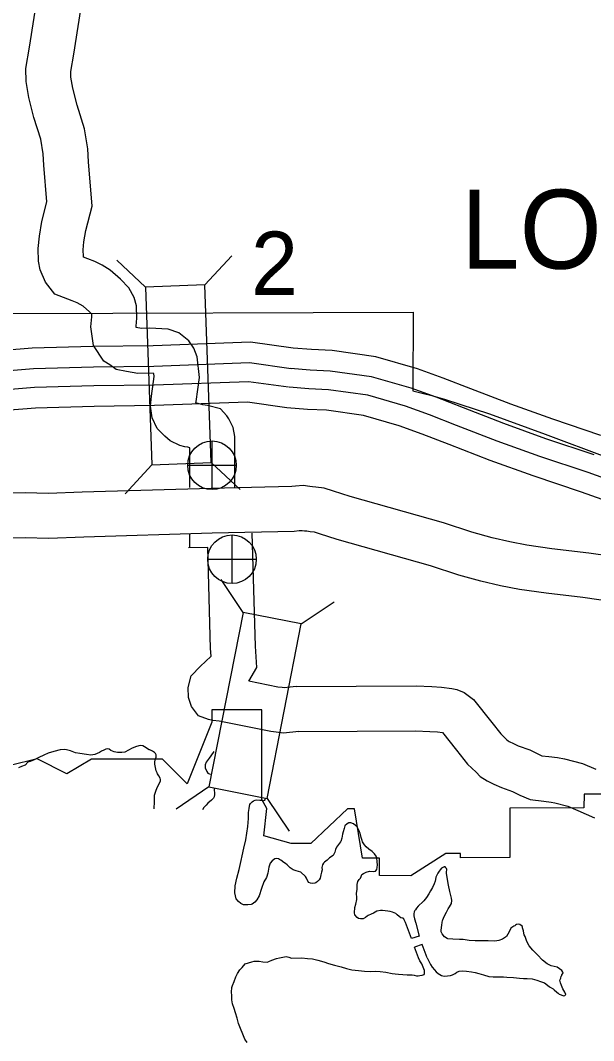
# Model space of a CAD drawing. Extents: x 1374139 to 1377472, y 1168351 to 1170484.
# Drawn here: x 1374342.2 to 1374380.5, y 1170108.2 to 1170176.4 of the extents above; entities that cross this region are included whole.
import ezdxf

# ---------------------------------------------------------------- set-up
doc = ezdxf.new("R2010")
doc.units = 0
doc.layers.add('Default', color=7, linetype='Continuous')

msp = doc.modelspace()

# ---------------------------------------------------------------- linework, layer by layer
at = {"layer": 'Default'}
for p, q in [((1374354.51, 1170158.728), (1374356.309, 1170160.66)), ((1374350.552, 1170158.587), (1374348.62, 1170160.387)), ((1374354.991, 1170145.055), (1374354.991, 1170148.305)), ((1374350.974, 1170146.715), (1374349.175, 1170144.783)), ((1374353.366, 1170146.68), (1374356.616, 1170146.68)), ((1374354.932, 1170146.855), (1374356.864, 1170145.056)), ((1374356.328, 1170138.779), (1374356.328, 1170142.029)), ((1374354.703, 1170140.404), (1374357.953, 1170140.404)), ((1374357.074, 1170136.849), (1374355.601, 1170139.04)), ((1374360.96, 1170136.087), (1374363.151, 1170137.559)), ((1374354.787, 1170125.191), (1374352.596, 1170123.718)), ((1374358.673, 1170124.429), (1374360.146, 1170122.238))]:
    msp.add_line(p, q, dxfattribs=at)
for points in [[(1374353.509, 1170145.193), (1374353.51, 1170147.852), (1374353.381, 1170147.888), (1374353.185, 1170147.904), (1374352.831, 1170148.01), (1374352.203, 1170148.31), (1374351.827, 1170148.623), (1374351.318, 1170149.141), (1374350.997, 1170149.855), (1374350.873, 1170150.636), (1374350.943, 1170151.302), (1374351.126, 1170152.608), (1374351.105, 1170152.815), (1374350.797, 1170152.828), (1374350.026, 1170152.804), (1374349.281, 1170152.948), (1374348.578, 1170153.082), (1374348.17, 1170153.389), (1374347.762, 1170153.623), (1374347.057, 1170154.682), (1374346.899, 1170155.919), (1374346.967, 1170156.605), (1374346.962, 1170156.771), (1374346.806, 1170156.926), (1374346.377, 1170157.308), (1374346.182, 1170157.43), (1374345.978, 1170157.531), (1374345.637, 1170157.656), (1374344.475, 1170158.103), (1374343.869, 1170158.911), (1374343.495, 1170159.733), (1374343.397, 1170160.316), (1374343.371, 1170161.17), (1374343.454, 1170161.979), (1374343.604, 1170162.97), (1374343.944, 1170164.268), (1374343.75, 1170166.735), (1374343.7, 1170167.484), (1374343.543, 1170168.457), (1374343.087, 1170169.912), (1374342.743, 1170171.257), (1374342.569, 1170172.308), (1374342.542, 1170173.189), (1374342.785, 1170174.617), (1374343.826, 1170181.294)], [(1374356.509, 1170145.213), (1374356.51, 1170148.608), (1374356.401, 1170149.203), (1374356.117, 1170149.786), (1374355.974, 1170149.988), (1374355.548, 1170150.457), (1374354.69, 1170150.675), (1374354.385, 1170150.723), (1374353.912, 1170150.854), (1374353.921, 1170150.937), (1374354.147, 1170152.552), (1374354.007, 1170153.918), (1374353.77, 1170154.497), (1374353.431, 1170155.001), (1374352.777, 1170155.526), (1374352.061, 1170155.778), (1374350.813, 1170155.83), (1374350.267, 1170155.813), (1374349.928, 1170155.878), (1374349.918, 1170155.961), (1374349.971, 1170156.502), (1374349.946, 1170157.322), (1374349.784, 1170157.876), (1374349.439, 1170158.538), (1374348.864, 1170159.11), (1374348.184, 1170159.717), (1374347.645, 1170160.054), (1374347.16, 1170160.293), (1374346.692, 1170160.464), (1374346.409, 1170160.573), (1374346.389, 1170160.617), (1374346.375, 1170161.062), (1374346.431, 1170161.601), (1374346.546, 1170162.363), (1374346.975, 1170163.998), (1374346.742, 1170166.954), (1374346.683, 1170167.825), (1374346.47, 1170169.148), (1374345.974, 1170170.732), (1374345.682, 1170171.875), (1374345.561, 1170172.6), (1374345.55, 1170172.981), (1374345.746, 1170174.134), (1374346.792, 1170180.841)], [(1374329.613, 1170138.255), (1374329.708, 1170138.541), (1374329.726, 1170138.75), (1374329.699, 1170139.004), (1374329.535, 1170139.631), (1374329.51, 1170140.385), (1374329.563, 1170140.94), (1374329.358, 1170141.587), (1374329.154, 1170142.331), (1374328.792, 1170142.955), (1374328.432, 1170143.6), (1374328.465, 1170156.813), (1374341.665, 1170156.809), (1374368.443, 1170156.907), (1374368.424, 1170151.663), (1374369.14, 1170151.48), (1374369.591, 1170151.367), (1374370.529, 1170151.106), (1374371.558, 1170150.76), (1374373.547, 1170150.111), (1374377.263, 1170148.749)], [(1374360.415, 1170154.5), (1374357.574, 1170154.894), (1374351.057, 1170154.663), (1374347.03, 1170154.609), (1374342.971, 1170154.494), (1374338.887, 1170154.165), (1374334.113, 1170153.797), (1374331.253, 1170153.534), (1374328.741, 1170153.158), (1374325.627, 1170152.948)], [(1374380.994, 1170148.672), (1374377.771, 1170149.751), (1374374.98, 1170150.751), (1374372.294, 1170151.787), (1374370.455, 1170152.506), (1374368.73, 1170153.132), (1374365.95, 1170153.928), (1374363.031, 1170154.336), (1374361.638, 1170154.408), (1374360.415, 1170154.5)], [(1374360.288, 1170153.13), (1374357.504, 1170153.516), (1374351.091, 1170153.288), (1374347.059, 1170153.234), (1374343.046, 1170153.12), (1374338.996, 1170152.794), (1374334.229, 1170152.426), (1374331.418, 1170152.168), (1374328.89, 1170151.79), (1374325.727, 1170151.577)], [(1374380.544, 1170147.373), (1374377.321, 1170148.452), (1374374.501, 1170149.462), (1374371.796, 1170150.506), (1374369.971, 1170151.219), (1374368.305, 1170151.823), (1374365.664, 1170152.58), (1374362.901, 1170152.966), (1374361.551, 1170153.036), (1374360.249, 1170153.134)], [(1374360.116, 1170151.892), (1374357.44, 1170152.263), (1374351.121, 1170152.038), (1374347.085, 1170151.984), (1374343.114, 1170151.872), (1374339.094, 1170151.548), (1374334.334, 1170151.181), (1374331.567, 1170150.926), (1374329.024, 1170150.546), (1374325.789, 1170150.328)], [(1374382.62, 1170145.304), (1374380.135, 1170146.192), (1374376.911, 1170147.27), (1374374.065, 1170148.29), (1374371.343, 1170149.34), (1374369.53, 1170150.049), (1374367.92, 1170150.633), (1374365.404, 1170151.354), (1374362.782, 1170151.721), (1374361.472, 1170151.788), (1374360.155, 1170151.888)], [(1374359.989, 1170150.521), (1374357.369, 1170150.885), (1374351.155, 1170150.664), (1374347.114, 1170150.609), (1374343.189, 1170150.498), (1374339.202, 1170150.177), (1374334.45, 1170149.811), (1374331.732, 1170149.561), (1374329.172, 1170149.178), (1374325.887, 1170148.956)], [(1374382.154, 1170144.01), (1374379.686, 1170144.892), (1374376.461, 1170145.971), (1374373.586, 1170147.001), (1374370.845, 1170148.059), (1374369.045, 1170148.762), (1374367.495, 1170149.324), (1374365.118, 1170150.006), (1374362.651, 1170150.351), (1374361.385, 1170150.416), (1374359.989, 1170150.521)], [(1374377.263, 1170148.749), (1374381.444, 1170147.21), (1374388.249, 1170144.705), (1374392.86, 1170142.998), (1374397.937, 1170141.128), (1374400.772, 1170140.018), (1374403.642, 1170139.032), (1374407.04, 1170137.79), (1374411.123, 1170136.344), (1374415.029, 1170134.925), (1374416.263, 1170134.537), (1374418.35, 1170133.902), (1374420.036, 1170133.479), (1374421.234, 1170133.218), (1374424.972, 1170132.498), (1374427.362, 1170132.068), (1374430.239, 1170131.538), (1374434.47, 1170130.748), (1374437.745, 1170130.134), (1374439.448, 1170129.81)], [(1374360.323, 1170145.263), (1374354.929, 1170145.135), (1374346.318, 1170144.88), (1374344.061, 1170144.8), (1374342.506, 1170144.832), (1374340.416, 1170144.798), (1374326.149, 1170144.849), (1374319.16, 1170144.904), (1374315.355, 1170144.888), (1374312.166, 1170144.83), (1374307.795, 1170144.845), (1374302.229, 1170144.924), (1374300.248, 1170144.932), (1374299.152, 1170144.986)], [(1374396.908, 1170138.701), (1374392.318, 1170139.331), (1374387.245, 1170139.983), (1374383.354, 1170140.359), (1374380.177, 1170140.815), (1374377.712, 1170141.106), (1374376.036, 1170141.34), (1374374.914, 1170141.558), (1374373.716, 1170141.844), (1374372.361, 1170142.215), (1374370.478, 1170142.834), (1374364.227, 1170144.584), (1374363.124, 1170144.946), (1374362.481, 1170145.158), (1374361.944, 1170145.214), (1374361.706, 1170145.25), (1374361.522, 1170145.27), (1374361.087, 1170145.321), (1374360.576, 1170145.284), (1374360.323, 1170145.263)], [(1374360.487, 1170142.266), (1374355.009, 1170142.136), (1374346.415, 1170141.881), (1374344.083, 1170141.799), (1374342.5, 1170141.832), (1374340.436, 1170141.798), (1374326.132, 1170141.849), (1374319.154, 1170141.904), (1374315.389, 1170141.888), (1374312.188, 1170141.83), (1374307.768, 1170141.845), (1374302.202, 1170141.924), (1374300.167, 1170141.932), (1374299.152, 1170141.982)], [(1374360.62, 1170131.904), (1374359.805, 1170131.816), (1374359.677, 1170131.833), (1374359.4, 1170131.868), (1374357.455, 1170132.25), (1374357.997, 1170133.176), (1374357.897, 1170134.588), (1374357.687, 1170142.155)], [(1374397.123, 1170135.644), (1374391.923, 1170136.357), (1374386.909, 1170137.002), (1374382.997, 1170137.38), (1374379.788, 1170137.84), (1374377.329, 1170138.13), (1374375.542, 1170138.38), (1374374.279, 1170138.625), (1374372.971, 1170138.938), (1374371.497, 1170139.342), (1374369.605, 1170139.963), (1374363.355, 1170141.713), (1374362.188, 1170142.096), (1374361.847, 1170142.208), (1374361.563, 1170142.238), (1374361.321, 1170142.274), (1374361.185, 1170142.289), (1374361.02, 1170142.309), (1374360.812, 1170142.294), (1374360.487, 1170142.266)], [(1374353.508, 1170141.159), (1374353.508, 1170142.075)], [(1374360.788, 1170128.904), (1374359.762, 1170128.794), (1374359.288, 1170128.859), (1374358.924, 1170128.904), (1374355.467, 1170129.582), (1374355.053, 1170129.64), (1374354.766, 1170129.698), (1374354.092, 1170129.944), (1374353.622, 1170130.564), (1374353.422, 1170131.178), (1374353.402, 1170131.832), (1374353.608, 1170132.611), (1374354.217, 1170133.262), (1374354.562, 1170133.563), (1374354.936, 1170133.93), (1374354.9, 1170134.439), (1374354.712, 1170141.189)], [(1374354.712, 1170141.189), (1374353.425, 1170141.159)], [(1374360.62, 1170131.904), (1374368.652, 1170131.943), (1374369.694, 1170131.897), (1374370.338, 1170131.863), (1374371.02, 1170131.775), (1374371.371, 1170131.693), (1374371.856, 1170131.494), (1374372.483, 1170131.044), (1374373.7, 1170129.508), (1374374.294, 1170128.738), (1374374.712, 1170128.349), (1374374.794, 1170128.269), (1374374.859, 1170128.228), (1374375.147, 1170128.086), (1374375.472, 1170127.934), (1374376.247, 1170127.668), (1374376.856, 1170127.359), (1374377.052, 1170127.273), (1374377.52, 1170127.22), (1374378.097, 1170127.153), (1374378.564, 1170127.07), (1374379.759, 1170126.753), (1374380.648, 1170126.377)], [(1374381.515, 1170124.717), (1374379.865, 1170124.706), (1374379.862, 1170123.801), (1374374.913, 1170123.77), (1374374.899, 1170120.475), (1374371.597, 1170120.454), (1374371.599, 1170120.755), (1374370.615, 1170120.753), (1374368.289, 1170119.264), (1374366.193, 1170119.268), (1374366.19, 1170120.441), (1374365.058, 1170120.445), (1374364.527, 1170123.74), (1374364.049, 1170123.741), (1374361.601, 1170121.422), (1374360.281, 1170121.424), (1374358.464, 1170121.923), (1374358.647, 1170123.757), (1374358.324, 1170124.351), (1374358.317, 1170130.338), (1374354.974, 1170130.344), (1374354.977, 1170129.521), (1374353.339, 1170125.397), (1374351.683, 1170127.05), (1374346.925, 1170127.059), (1374345.289, 1170126.072), (1374343.295, 1170127.066), (1374341.486, 1170126.625)], [(1374360.788, 1170128.904), (1374368.594, 1170128.943), (1374369.55, 1170128.901), (1374370.066, 1170128.874), (1374370.41, 1170128.829), (1374371.336, 1170127.66), (1374372.069, 1170126.71), (1374372.645, 1170126.174), (1374372.928, 1170125.9), (1374373.388, 1170125.609), (1374373.845, 1170125.383), (1374374.345, 1170125.148), (1374375.076, 1170124.898), (1374375.576, 1170124.644), (1374376.265, 1170124.344), (1374377.177, 1170124.239), (1374377.661, 1170124.183), (1374377.916, 1170124.138), (1374378.786, 1170123.908), (1374379.446, 1170123.628), (1374380.555, 1170123.127)], [(1374351.14, 1170127.501), (1374351.017, 1170127.578), (1374350.886, 1170127.644), (1374350.825, 1170127.662), (1374350.785, 1170127.661), (1374350.479, 1170127.882), (1374350.377, 1170127.929), (1374350.197, 1170127.954), (1374349.939, 1170127.896), (1374349.663, 1170127.787), (1374349.397, 1170127.648), (1374349.161, 1170127.521), (1374348.973, 1170127.485), (1374348.683, 1170127.486), (1374348.441, 1170127.549), (1374348.229, 1170127.632), (1374348.116, 1170127.719), (1374348.006, 1170127.736), (1374347.887, 1170127.712), (1374347.759, 1170127.658), (1374347.611, 1170127.583), (1374347.464, 1170127.498), (1374347.158, 1170127.369), (1374346.89, 1170127.32), (1374346.589, 1170127.361), (1374346.158, 1170127.418), (1374345.866, 1170127.479), (1374345.533, 1170127.599), (1374345.261, 1170127.671), (1374345.111, 1170127.697), (1374344.831, 1170127.678), (1374344.426, 1170127.555), (1374344.03, 1170127.443), (1374343.744, 1170127.324), (1374343.409, 1170127.163), (1374343.094, 1170127.013), (1374342.838, 1170126.884), (1374342.67, 1170126.839), (1374342.506, 1170126.644), (1374342.249, 1170126.555), (1374342.052, 1170126.469)], [(1374351.123, 1170123.731), (1374351.141, 1170124.212), (1374351.146, 1170124.383), (1374351.147, 1170124.653), (1374351.257, 1170124.988), (1374351.35, 1170125.211), (1374351.483, 1170125.436), (1374351.548, 1170125.598), (1374351.545, 1170125.689), (1374351.522, 1170125.778), (1374351.428, 1170125.936), (1374351.343, 1170126.074), (1374351.322, 1170126.133), (1374351.267, 1170126.272), (1374351.211, 1170126.491), (1374351.164, 1170126.71), (1374351.17, 1170126.85), (1374351.195, 1170127.002), (1374351.25, 1170127.174), (1374351.255, 1170127.334), (1374351.212, 1170127.423), (1374351.14, 1170127.501)], [(1374355.103, 1170127.551), (1374354.922, 1170127.277), (1374354.797, 1170127.123), (1374354.606, 1170126.856), (1374354.542, 1170126.664), (1374354.538, 1170126.463), (1374354.655, 1170126.216), (1374354.718, 1170126.117), (1374354.865, 1170126.045)], [(1374355.14, 1170125.082), (1374355.152, 1170124.687), (1374355.146, 1170124.536), (1374355.099, 1170124.454), (1374354.963, 1170124.32), (1374354.72, 1170124.112), (1374354.594, 1170123.967), (1374354.449, 1170123.822), (1374354.349, 1170123.666)], [(1374360.932, 1170119.505), (1374360.613, 1170119.58), (1374360.421, 1170119.654), (1374360.217, 1170119.788), (1374360.103, 1170119.905), (1374360.011, 1170119.992), (1374359.908, 1170120.069), (1374359.796, 1170120.156), (1374359.582, 1170120.3), (1374359.511, 1170120.338), (1374359.429, 1170120.386), (1374359.329, 1170120.403), (1374359.189, 1170120.398), (1374359.013, 1170120.262), (1374358.889, 1170120.098), (1374358.787, 1170119.844), (1374358.729, 1170119.441), (1374358.628, 1170119.147), (1374358.457, 1170118.851), (1374358.301, 1170118.405), (1374358.146, 1170117.919), (1374357.995, 1170117.654), (1374357.86, 1170117.489), (1374357.674, 1170117.363), (1374357.615, 1170117.341), (1374357.376, 1170117.314), (1374357.106, 1170117.315), (1374356.923, 1170117.41), (1374356.76, 1170117.545), (1374356.604, 1170117.721), (1374356.512, 1170118.129), (1374356.538, 1170118.591), (1374356.652, 1170119.106), (1374356.814, 1170119.673), (1374356.945, 1170120.289), (1374357.015, 1170120.602), (1374357.12, 1170121.107), (1374357.252, 1170121.662), (1374357.329, 1170122.096), (1374357.385, 1170122.549), (1374357.428, 1170123.092), (1374357.436, 1170123.493), (1374357.468, 1170123.745), (1374357.493, 1170123.916), (1374357.52, 1170124.017), (1374357.557, 1170124.089), (1374357.674, 1170124.193), (1374357.762, 1170124.266), (1374357.88, 1170124.309), (1374357.999, 1170124.333), (1374358.2, 1170124.319), (1374358.29, 1170124.302), (1374358.391, 1170124.275), (1374358.461, 1170124.277), (1374358.53, 1170124.299), (1374358.567, 1170124.381), (1374358.549, 1170124.448)], [(1374364.025, 1170122.739), (1374363.878, 1170122.587), (1374363.83, 1170122.426), (1374363.754, 1170122.194), (1374363.727, 1170122.034), (1374363.661, 1170121.782), (1374363.595, 1170121.551), (1374363.586, 1170121.521), (1374363.449, 1170121.348), (1374363.322, 1170121.176), (1374363.254, 1170121.005), (1374363.197, 1170120.834), (1374363.091, 1170120.622), (1374362.854, 1170120.448), (1374362.687, 1170120.305), (1374362.519, 1170120.172), (1374362.44, 1170120.101), (1374362.382, 1170119.989), (1374362.335, 1170119.819), (1374362.348, 1170119.659), (1374362.32, 1170119.508), (1374362.273, 1170119.327), (1374362.217, 1170119.106), (1374362.159, 1170118.985), (1374362.041, 1170118.873), (1374361.932, 1170118.791), (1374361.863, 1170118.77), (1374361.733, 1170118.748), (1374361.573, 1170118.765), (1374361.463, 1170118.813), (1374361.401, 1170118.892), (1374361.308, 1170119.091), (1374361.236, 1170119.22), (1374360.932, 1170119.505)], [(1374368.32, 1170115.069), (1374367.928, 1170116.135), (1374367.845, 1170116.314), (1374367.845, 1170116.324), (1374367.814, 1170116.374), (1374367.774, 1170116.423), (1374367.704, 1170116.432), (1374367.613, 1170116.451), (1374367.502, 1170116.539), (1374367.371, 1170116.647), (1374367.279, 1170116.736), (1374367.058, 1170116.822), (1374366.898, 1170116.869), (1374366.737, 1170116.897), (1374366.397, 1170116.931), (1374366.247, 1170116.929), (1374366.008, 1170116.885), (1374365.781, 1170116.771), (1374365.622, 1170116.699), (1374365.424, 1170116.595), (1374365.355, 1170116.554), (1374365.256, 1170116.482), (1374365.098, 1170116.39), (1374364.918, 1170116.377), (1374364.788, 1170116.415), (1374364.697, 1170116.463), (1374364.544, 1170116.661), (1374364.522, 1170116.791), (1374364.536, 1170117.131), (1374364.602, 1170117.363), (1374364.667, 1170117.674), (1374364.665, 1170117.814), (1374364.661, 1170118.074), (1374364.706, 1170118.365), (1374364.701, 1170118.666), (1374364.738, 1170118.867), (1374364.835, 1170119.008), (1374364.914, 1170119.1), (1374364.972, 1170119.211), (1374365.019, 1170119.352), (1374365.128, 1170119.414), (1374365.307, 1170119.497), (1374365.515, 1170119.56), (1374365.765, 1170119.554), (1374365.925, 1170119.567), (1374366.003, 1170119.678), (1374366.03, 1170119.819), (1374366.047, 1170119.999), (1374366.044, 1170120.199), (1374366.02, 1170120.449), (1374365.968, 1170120.569), (1374365.866, 1170120.727), (1374365.703, 1170120.875), (1374365.481, 1170121.041), (1374365.299, 1170121.188), (1374365.177, 1170121.337), (1374365.054, 1170121.525), (1374365.022, 1170121.614), (1374364.969, 1170121.824), (1374364.894, 1170122.113), (1374364.863, 1170122.192), (1374364.801, 1170122.301), (1374364.718, 1170122.49), (1374364.688, 1170122.52), (1374364.576, 1170122.628), (1374364.445, 1170122.736), (1374364.264, 1170122.793), (1374364.134, 1170122.801), (1374364.025, 1170122.739)], [(1374370.358, 1170115.965), (1374370.385, 1170116.145), (1374370.403, 1170116.276), (1374370.422, 1170116.316), (1374370.518, 1170116.528), (1374370.673, 1170116.821), (1374370.79, 1170117.043), (1374370.877, 1170117.185), (1374370.935, 1170117.286), (1374371.003, 1170117.407), (1374371.03, 1170117.608), (1374371.007, 1170117.767), (1374370.912, 1170118.126), (1374370.9, 1170118.206), (1374370.794, 1170118.625), (1374370.705, 1170119.134), (1374370.671, 1170119.424), (1374370.679, 1170119.534), (1374370.687, 1170119.634), (1374370.697, 1170119.675), (1374370.686, 1170119.704), (1374370.665, 1170119.754), (1374370.625, 1170119.793), (1374370.584, 1170119.853), (1374370.544, 1170119.852), (1374370.504, 1170119.852), (1374370.326, 1170119.759), (1374370.247, 1170119.667), (1374370.179, 1170119.566), (1374370.101, 1170119.435), (1374370.024, 1170119.303), (1374369.956, 1170119.162), (1374369.938, 1170119.011), (1374369.91, 1170118.891), (1374369.844, 1170118.71), (1374369.738, 1170118.468), (1374369.601, 1170118.245), (1374369.485, 1170118.043), (1374369.329, 1170117.8), (1374369.153, 1170117.587), (1374369.045, 1170117.475), (1374368.848, 1170117.302), (1374368.779, 1170117.221), (1374368.671, 1170117.099), (1374368.593, 1170116.987), (1374368.554, 1170116.937), (1374368.506, 1170116.846), (1374368.488, 1170116.725), (1374368.49, 1170116.575), (1374368.533, 1170116.386), (1374368.628, 1170116.087)], [(1374368.628, 1170116.087), (1374368.832, 1170115.219), (1374368.32, 1170115.069)], [(1374369.375, 1170113.776), (1374369.592, 1170113.329), (1374369.715, 1170113.161), (1374369.857, 1170112.983), (1374369.97, 1170112.845), (1374370.111, 1170112.727), (1374370.333, 1170112.601), (1374370.503, 1170112.563), (1374370.733, 1170112.567), (1374370.942, 1170112.59), (1374371.071, 1170112.653), (1374371.26, 1170112.736), (1374371.358, 1170112.818), (1374371.507, 1170112.88), (1374371.766, 1170112.904), (1374372.006, 1170112.888), (1374372.336, 1170112.843), (1374372.597, 1170112.798), (1374372.828, 1170112.741), (1374373.139, 1170112.646), (1374373.5, 1170112.542), (1374373.8, 1170112.507), (1374374.15, 1170112.513), (1374374.489, 1170112.498), (1374374.709, 1170112.492), (1374375.139, 1170112.469), (1374375.549, 1170112.425), (1374375.829, 1170112.4), (1374376.069, 1170112.394), (1374376.399, 1170112.369), (1374376.549, 1170112.331), (1374376.7, 1170112.284), (1374376.961, 1170112.208), (1374377.212, 1170112.102), (1374377.415, 1170111.945), (1374377.566, 1170111.837), (1374377.798, 1170111.701), (1374377.859, 1170111.642), (1374378.051, 1170111.495), (1374378.142, 1170111.416), (1374378.213, 1170111.357), (1374378.344, 1170111.3), (1374378.495, 1170111.232), (1374378.584, 1170111.253), (1374378.653, 1170111.335), (1374378.591, 1170111.484), (1374378.457, 1170111.712), (1374378.354, 1170111.92), (1374378.281, 1170112.119), (1374378.258, 1170112.279), (1374378.306, 1170112.41), (1374378.343, 1170112.561), (1374378.373, 1170112.591), (1374378.392, 1170112.642), (1374378.451, 1170112.723), (1374378.46, 1170112.763), (1374378.449, 1170112.823), (1374378.387, 1170112.942), (1374378.074, 1170113.147), (1374377.663, 1170113.241), (1374377.391, 1170113.376), (1374377.088, 1170113.612), (1374376.762, 1170113.977), (1374376.447, 1170114.292), (1374376.193, 1170114.588), (1374376.048, 1170114.876), (1374375.923, 1170115.195), (1374375.871, 1170115.324), (1374375.839, 1170115.433), (1374375.807, 1170115.573), (1374375.754, 1170115.772), (1374375.753, 1170115.822), (1374375.722, 1170115.892), (1374375.571, 1170116), (1374375.48, 1170116.018), (1374375.361, 1170115.996), (1374375.292, 1170115.955), (1374375.242, 1170115.924), (1374375.163, 1170115.883), (1374374.975, 1170115.75), (1374374.859, 1170115.518), (1374374.675, 1170115.214), (1374374.408, 1170115.02), (1374374.16, 1170114.926), (1374373.901, 1170114.901), (1374373.451, 1170114.904), (1374373.191, 1170114.91), (1374372.842, 1170114.914), (1374372.712, 1170114.912), (1374372.582, 1170114.91), (1374372.192, 1170114.933), (1374371.782, 1170114.997), (1374371.532, 1170115.013), (1374371.102, 1170115.016), (1374370.752, 1170115.05), (1374370.712, 1170115.06), (1374370.541, 1170115.177), (1374370.377, 1170115.384), (1374370.315, 1170115.514), (1374370.314, 1170115.624), (1374370.358, 1170115.965)], [(1374360.986, 1170113.78), (1374361.376, 1170113.726), (1374361.716, 1170113.712), (1374362.057, 1170113.617), (1374362.458, 1170113.503), (1374362.78, 1170113.408), (1374363.191, 1170113.295), (1374363.632, 1170113.172), (1374363.984, 1170113.058), (1374364.335, 1170112.983), (1374364.795, 1170112.921), (1374365.195, 1170112.877), (1374365.555, 1170112.873), (1374365.894, 1170112.889), (1374366.244, 1170112.874), (1374366.604, 1170112.82), (1374367.045, 1170112.737), (1374367.245, 1170112.71), (1374367.465, 1170112.684), (1374367.755, 1170112.669), (1374368.045, 1170112.653), (1374368.375, 1170112.649), (1374368.515, 1170112.611), (1374368.666, 1170112.583), (1374368.785, 1170112.575), (1374368.895, 1170112.597), (1374369.045, 1170112.61), (1374369.173, 1170112.672), (1374369.202, 1170112.742), (1374369.189, 1170112.932), (1374369.012, 1170113.37), (1374368.889, 1170113.588), (1374368.796, 1170113.777), (1374368.53, 1170114.499)], [(1374369.375, 1170113.776), (1374369.041, 1170114.662), (1374368.53, 1170114.499)], [(1374357.339, 1170108.116), (1374357.192, 1170108.352), (1374356.76, 1170109.402), (1374356.67, 1170109.74), (1374356.568, 1170110.108), (1374356.47, 1170110.386), (1374356.37, 1170110.704), (1374356.322, 1170110.983), (1374356.313, 1170111.273), (1374356.296, 1170111.494), (1374356.327, 1170111.795), (1374356.362, 1170111.937), (1374356.475, 1170112.191), (1374356.574, 1170112.515), (1374356.688, 1170112.729), (1374356.85, 1170112.985), (1374357.005, 1170113.14), (1374357.207, 1170113.377), (1374357.435, 1170113.444), (1374357.653, 1170113.501), (1374357.801, 1170113.546), (1374357.941, 1170113.56), (1374358.141, 1170113.546), (1374358.382, 1170113.513), (1374358.682, 1170113.493), (1374358.801, 1170113.526), (1374358.998, 1170113.613), (1374359.304, 1170113.742), (1374359.512, 1170113.779), (1374359.939, 1170113.862), (1374360.13, 1170113.828), (1374360.312, 1170113.764), (1374360.986, 1170113.78)]]:
    msp.add_lwpolyline(points, dxfattribs=at)
for points in [[(1374354.932, 1170146.855), (1374354.51, 1170158.728), (1374350.552, 1170158.587), (1374350.974, 1170146.715)], [(1374358.673, 1170124.429), (1374360.96, 1170136.087), (1374357.074, 1170136.849), (1374354.787, 1170125.191)]]:
    msp.add_lwpolyline(points, close=True, dxfattribs=at)
for centre in [(1374354.991, 1170146.68), (1374356.328, 1170140.404)]:
    msp.add_circle(centre, 1.625, dxfattribs=at)

# ---------------------------------------------------------------- texts
for s, height, p in [('LONDON', 5.28, (1374371.632, 1170159.81)), ('2', 4.224, (1374357.601, 1170158.063))]:
    msp.add_text(s, height=height, dxfattribs=at).set_placement(p)

doc.saveas('drawing.dxf')
